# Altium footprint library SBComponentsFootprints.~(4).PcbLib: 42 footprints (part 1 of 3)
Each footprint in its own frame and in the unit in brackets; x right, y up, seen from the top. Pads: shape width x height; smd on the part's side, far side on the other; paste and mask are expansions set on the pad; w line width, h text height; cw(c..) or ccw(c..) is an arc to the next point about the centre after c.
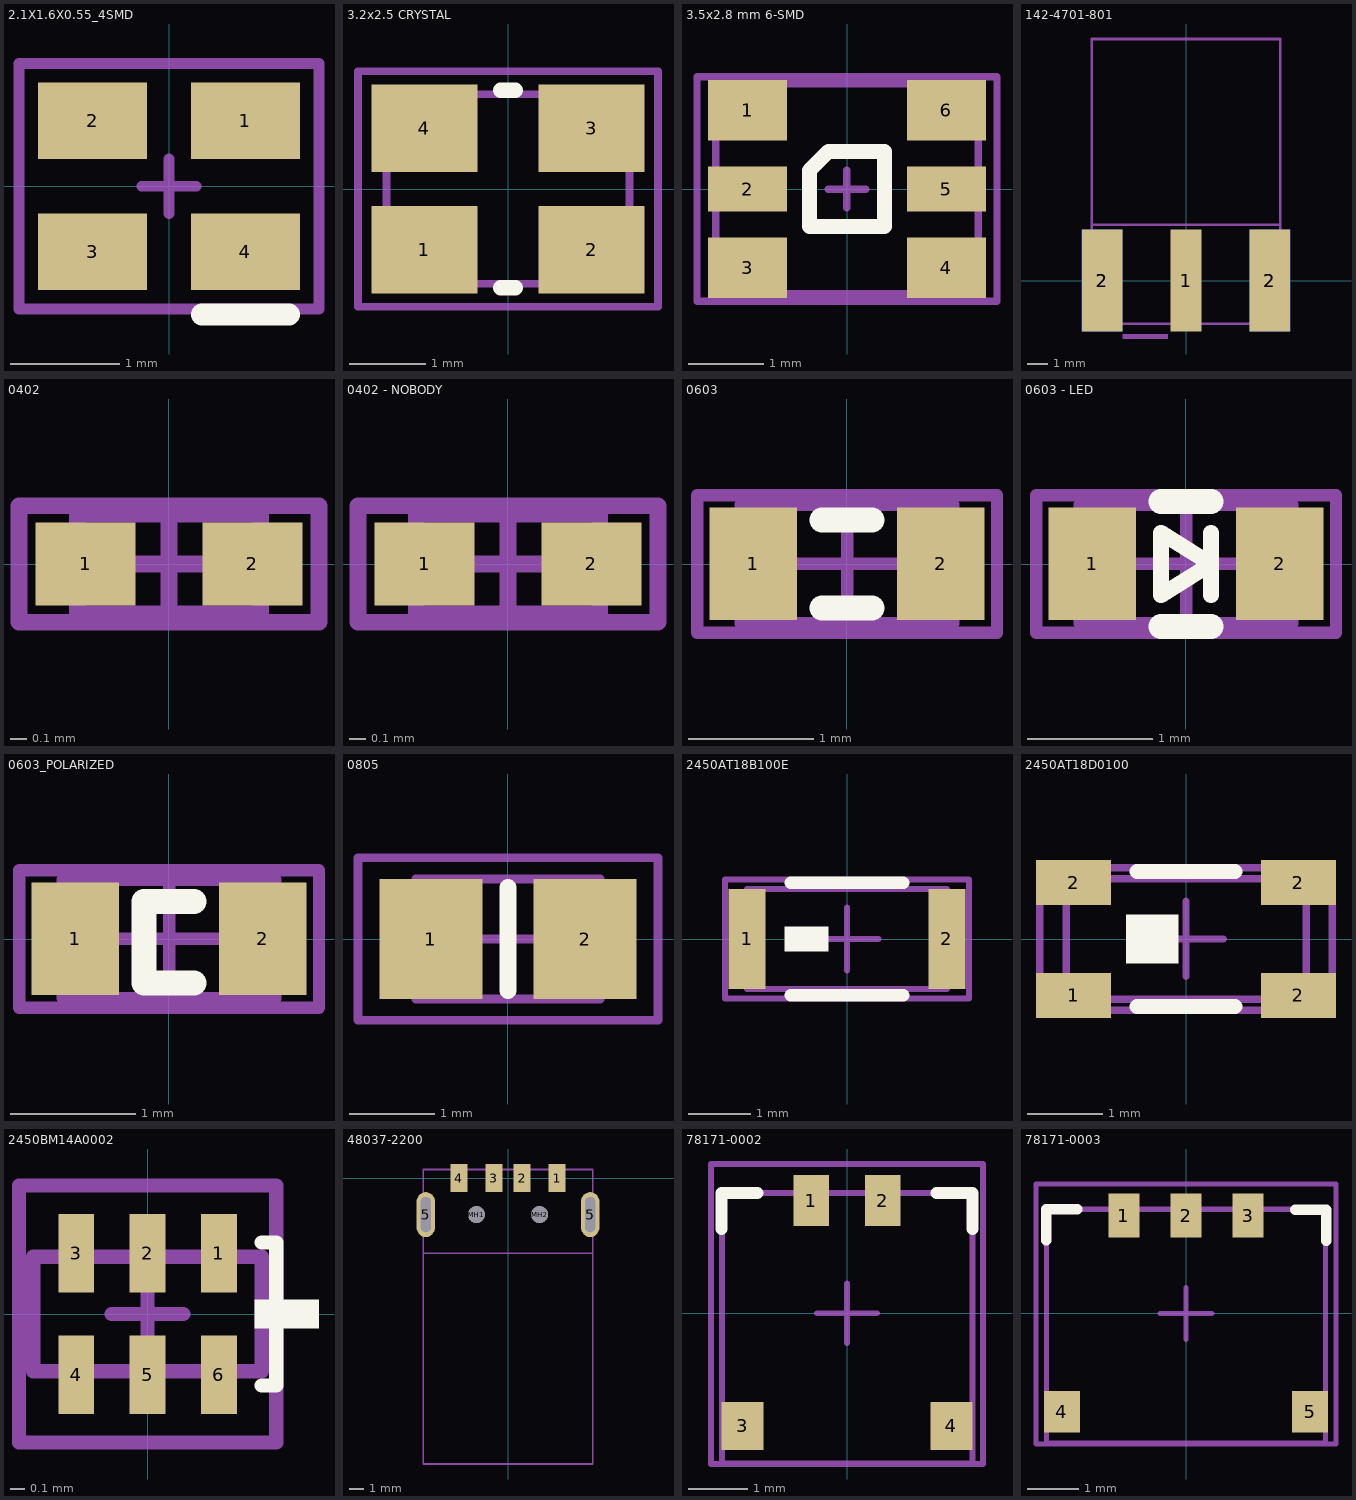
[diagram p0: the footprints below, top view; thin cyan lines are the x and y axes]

## 2.1X1.6X0.55_4SMD [mm]
height 0.55
pads (4):
  rect 1x0.7 smd: 1(0.7,0.6) 2(-0.7,0.6) 3(-0.7,-0.6) 4(0.7,-0.6)
Top Overlay:
  lines w0.2: 0.3,-1.175 1.1,-1.175
Mechanical 15:
  lines w0.1: -0.25,0 0.25,0 ; 0,-0.25 0,0.25 ; -1.375,-1.125 -1.375,1.125 1.375,1.125 1.375,-1.125 -1.375,-1.125
3D body: height 0.55, standoff 0, extent -1.05,-0.8 1.05,0.8

## 3.2x2.5 CRYSTAL [mm]
height 0.8
pads (4):
  rect 1.4x1.15 smd: 1(-1.1,-0.8) 2(1.1,-0.8) 3(1.1,0.8) 4(-1.1,0.8)
Top Overlay:
  lines w0.2: -0.1,-1.3 0.1,-1.3 ; -0.1,1.3 0.1,1.3
Mechanical 1:
  lines w0.1: -1.6,-1.25 -1.6,1.25 1.6,1.25 1.6,-1.25 -1.6,-1.25
Mechanical 15:
  lines w0.1: -1.975,-1.55 1.975,-1.55 1.975,1.55 -1.975,1.55 -1.975,-1.55
3D body: height 0.8, standoff 0, extent -1.6,-1.25 1.6,1.25

## 3.5x2.8 mm 6-SMD [mm] "3.5 x 2.8 mm 6-SMD Flat Leads"
height 0.6
pads (6):
  rect 1.05x0.8 smd: 1(-1.325,1.05) 3(-1.325,-1.05) 4(1.325,-1.05) 6(1.325,1.05)
  rect 1.05x0.6 smd: 2(-1.325,0) 5(1.325,0)
Top Overlay:
  lines w0.2: -0.5,-0.5 0.5,-0.5 0.5,0.5 -0.25,0.5 -0.5,0.25 -0.5,-0.5
Mechanical 13:
  lines w0.1: -1.75,-1.4 -1.75,1.4 1.75,1.4 1.75,-1.4 -1.75,-1.4
Mechanical 15:
  lines w0.1: -0.25,0 0.25,0 ; 0,-0.25 0,0.25 ; -2,-1.5 2,-1.5 2,1.5 -2,1.5 -2,-1.5
3D body "27979.stp": height 0.6, standoff 0, extent -1.75,-1.4 1.75,1.4

## 142-4701-801 [mil]
pads (5):
  rect 60x200 smd: 1(0,0)
  rect 80x200 smd: 2(-165,0) 2(165,0)
  rect 80x200 smd far side: 2(-165,0) 2(165,0)
Mechanical 1:
  rectangle: -125,-115 -35,-105
  lines w5: -185,110 185,110 ; -185,-85 -185,475 185,475 185,-85 -185,-85
  text "PCB edge" at -170,130 h23.62
3D body "User Library-Johnson Components SMA - 50 Ohm Connectors 142-0701-801.step": height 171.35, standoff -140.47, extent -187.4,-85.11 187.41,476.7

## 0402 [mm] "Chip Body 1.0 x 0.5 mm (LxW typ)"
height 0.55
pads (2):
  rect 0.6x0.5 smd: 1(-0.5,0) 2(0.5,0)
Mechanical 13:
  lines w0.1: -0.55,-0.3 -0.55,0.3 0.55,0.3 0.55,-0.3 -0.55,-0.3
Mechanical 15:
  lines w0.1: -0.3,0 0.3,0 ; 0,-0.3 0,0.3 ; -0.9,-0.35 -0.9,0.35 0.9,0.35 0.9,-0.35 -0.9,-0.35
3D body: height 0.55, standoff 0, extent -0.55,-0.3 0.55,0.3

## 0402 - NOBODY [mm] "Chip Body 1.0 x 0.5 mm (LxW typ)"
pads (2):
  rect 0.6x0.5 smd: 1(-0.5,0) 2(0.5,0)
Mechanical 13:
  lines w0.1: -0.55,-0.3 -0.55,0.3 0.55,0.3 0.55,-0.3 -0.55,-0.3
Mechanical 15:
  lines w0.1: -0.3,0 0.3,0 ; 0,-0.3 0,0.3 ; -0.9,-0.35 -0.9,0.35 0.9,0.35 0.9,-0.35 -0.9,-0.35
3D body: height 0, standoff 0, extent -0.55,-0.3 0.55,0.3

## 0603 [mm] "Chip Body 1.6 x 0.8 mm (LxW typ)"
height 0.87
pads (2):
  rect 0.7x0.9 smd: 1(-0.75,0) 2(0.75,0)
Top Overlay:
  lines w0.2: -0.2,-0.35 0.2,-0.35 ; -0.2,0.35 0.2,0.35
Mechanical 13:
  lines w0.1: -0.85,-0.475 -0.85,0.475 0.85,0.475 0.85,-0.475 -0.85,-0.475
Mechanical 15:
  lines w0.1: -0.475,0 0.475,0 ; 0,-0.475 0,0.475 ; -1.2,-0.55 -1.2,0.55 1.2,0.55 1.2,-0.55 -1.2,-0.55
3D body: height 0.9, standoff 0, extent -0.85,-0.475 0.85,0.475

## 0603 - LED [mm] "Chip Body 1.6 x 0.8 mm (LxW typ)"
height 0.87
pads (2):
  rect 0.7x0.9 smd: 1(-0.75,0) 2(0.75,0)
Top Overlay:
  lines w0.125: 0.2,-0.25 0.2,0.25 ; -0.2,-0.25 -0.2,0.25 0.2,0 -0.2,-0.25
  lines w0.2: -0.2,-0.5 0.2,-0.5 ; -0.2,0.5 0.2,0.5
Mechanical 13:
  lines w0.1: -0.85,-0.475 0.85,-0.475 0.85,0.475 -0.85,0.475 -0.85,-0.475
Mechanical 15:
  lines w0.1: -0.475,0 0.475,0 ; 0,-0.475 0,0.475 ; -1.2,-0.55 1.2,-0.55 1.2,0.55 -1.2,0.55 -1.2,-0.55
3D body: height 0.9, standoff 0, extent -0.85,-0.475 0.85,0.475

## 0603_POLARIZED [mm] "Chip Body 1.6 x 0.8 mm (LxW typ)"
height 0.87
pads (2):
  rect 0.7x0.9 smd: 1(-0.75,0) 2(0.75,0)
Top Overlay:
  lines w0.2: 0.2,-0.35 -0.2,-0.35 -0.2,0.3 0.2,0.3
Mechanical 13:
  lines w0.1: -0.85,-0.475 -0.85,0.475 0.85,0.475 0.85,-0.475 -0.85,-0.475
Mechanical 15:
  lines w0.1: -0.475,0 0.475,0 ; 0,-0.475 0,0.475 ; -1.2,-0.55 -1.2,0.55 1.2,0.55 1.2,-0.55 -1.2,-0.55
3D body: height 0.9, standoff 0, extent -0.85,-0.475 0.85,0.475

## 0805 [mm] "Chip Body 2.0 x 1.2 mm (LxW typ)"
height 1.3
pads (2):
  rect 1.2x1.4 smd: 1(-0.9,0) 2(0.9,0)
Top Overlay:
  lines w0.2: 0,-0.6 0,0.6
Mechanical 13:
  lines w0.1: -1.075,-0.7 1.075,-0.7 1.075,0.7 -1.075,0.7 -1.075,-0.7
Mechanical 15:
  lines w0.1: -0.5,0 0.5,0 ; 0,-0.5 0,0.5 ; -1.75,-0.95 1.75,-0.95 1.75,0.95 -1.75,0.95 -1.75,-0.95
3D body: height 1.3, standoff 0, extent -1.075,-0.7 1.075,0.7

## 2450AT18B100E [mm] "ANTENNA CHIP 2.4GHZ"
height 1.3
pads (2):
  rect 0.6x1.6 smd: 1(-1.6,0) 2(1.6,0)
Top Overlay:
  rectangle: -1,-0.2 -0.3,0.2
  lines w0.2: -0.9,-0.9 0.9,-0.9 ; -0.9,0.9 0.9,0.9
Mechanical 1:
  lines w0.1: -1.6,-0.8 1.6,-0.8 1.6,0.8 -1.6,0.8 -1.6,-0.8
Mechanical 15:
  lines w0.1: -0.5,0 0.5,0 ; 0,-0.5 0,0.5 ; -1.95,-0.95 1.95,-0.95 1.95,0.95 -1.95,0.95 -1.95,-0.95
3D body: height 1.3, standoff 0, extent -1.6,-0.8 1.6,0.8

## 2450AT18D0100 [mm] "ANTENNA CHIP 2.4GHZ"
height 1.3
pads (4):
  rect 1x0.6 smd: 1(-1.5,-0.75) 2(-1.5,0.75) 2(1.5,-0.75) 2(1.5,0.75)
Top Overlay:
  rectangle: -0.8,-0.325 -0.1,0.325
  lines w0.2: -0.65,-0.9 0.65,-0.9 ; -0.65,0.9 0.65,0.9
Mechanical 1:
  lines w0.1: -1.6,-0.8 1.6,-0.8 1.6,0.8 -1.6,0.8 -1.6,-0.8
Mechanical 15:
  lines w0.1: -0.5,0 0.5,0 ; 0,-0.5 0,0.5 ; -1.95,-0.95 1.95,-0.95 1.95,0.95 -1.95,0.95 -1.95,-0.95
3D body: height 1.3, standoff 0, extent -1.6,-0.8 1.6,0.8

## 2450BM14A0002 [mm] "2.45 GHz Impedance Matched Balun-Filter: Optimized for Nordic's Chipset nRF24L01"
height 0.6
pads (6):
  rect 0.25x0.55 smd: 1(0.5,0.425) 2(0,0.425) 3(-0.5,0.425) 4(-0.5,-0.425) 5(0,-0.425) 6(0.5,-0.425)
Top Overlay:
  rectangle: 0.75,-0.1 1.2,0.1
  lines w0.1: 0.8,-0.5 0.9,-0.5 0.9,0.5 0.8,0.5
Mechanical 13:
  lines w0.1: -0.8,-0.4 0.8,-0.4 0.8,0.4 -0.8,0.4 -0.8,-0.4
Mechanical 15:
  lines w0.1: -0.25,0 0.25,0 ; 0,-0.25 0,0.25 ; -0.9,-0.9 0.9,-0.9 0.9,0.9 -0.9,0.9 -0.9,-0.9
3D body: height 0.6, standoff 0, extent -0.8,-0.4 0.8,0.4

## 48037-2200 [mm] "Molex 48037-2200 USB Type A Receptacle"
height 2.1
pads (8):
  rect 1.2x2 smd: 1(3.5,0) 2(1,0) 3(-1,0) 4(-3.5,0)
  oval 1.3x3.2 hole 0.7 slot 2.5 at 90 deg: 5(-5.85,-2.6) 5(5.85,-2.6)
  round 1.2 hole 1.2 paste-2539.97 mask+0: MH1(-2.25,-2.6) MH2(2.25,-2.6)
Mechanical 1:
  lines w0.125: -6.025,-5.35 6.025,-5.35 ; -6.025,-20.35 -6.025,0.6 6.025,0.6 6.025,-20.35 -6.025,-20.35 ; -6.025,-20.35 -6.025,-20.35
  text "PCB edge" at -5.825,-6.15 h0.6
3D body "480372200.stp": height 2.1, standoff -2.4, extent -6.025,-20.35 6.025,0.6

## 78171-0002 [mm]
height 1.55
pads (4):
  rect 0.6x0.85 smd: 1(-0.6,1.888) 2(0.6,1.888)
  rect 0.7x0.8 smd: 3(-1.75,-1.887) 4(1.75,-1.887)
Top Overlay:
  lines w0.2: -2.1,1.413 -2.1,2.013 -1.5,2.013 ; 1.5,2.013 2.1,2.013 2.1,1.413
Mechanical 1:
  lines w0.1: -2.095,-2.512 -2.095,2.013 2.1,2.013 2.1,-2.512 -2.095,-2.512
Mechanical 15:
  lines w0.1: -0.5,0 0.5,0 ; 0,-0.5 0,0.5 ; -2.275,-2.525 2.275,-2.525 2.275,2.5 -2.275,2.5 -2.275,-2.525
3D body "781710002.stp": height 1.45, standoff 0, extent -2.1,-2.512 2.1,2.018

## 78171-0003 [mm]
height 1.55
pads (5):
  rect 0.6x0.85 smd: 1(-1.2,1.888) 2(0,1.888) 3(1.2,1.888)
  rect 0.7x0.8 smd: 4(-2.4,-1.9) 5(2.4,-1.9)
Top Overlay:
  lines w0.2: -2.7,1.413 -2.7,2.013 -2.1,2.013 ; 2.113,2 2.713,2 2.713,1.4
Mechanical 1:
  lines w0.1: -2.7,-2.512 -2.7,2.013 2.7,2.013 2.7,-2.512 -2.7,-2.512
Mechanical 15:
  lines w0.1: -0.5,0 0.5,0 ; 0,-0.5 0,0.5 ; -2.9,-2.525 2.9,-2.525 2.9,2.5 -2.9,2.5 -2.9,-2.525
3D body "781710003.stp": height 1.46, standoff 0.01, extent -2.7,-2.5 2.7,2.03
